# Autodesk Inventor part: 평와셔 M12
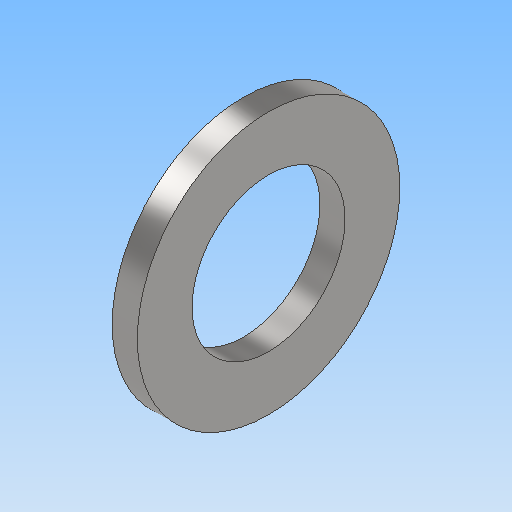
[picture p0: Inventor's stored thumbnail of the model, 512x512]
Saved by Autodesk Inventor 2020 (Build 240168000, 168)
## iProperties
Created: 2024-07
Part Number: 평와셔 M12
Material: 강철, 연강
Description: 평면 와셔
Document SubType Name: Modeling
Designer: oem
Density: 7.85 g/cm^3
Appearance: 기본값
Author: jhkim
Sending System: Autodesk Inventor 2025
Preprocessor: ST-DEVELOPER v20
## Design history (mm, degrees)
feature "Solid1"
node "솔리드1"
